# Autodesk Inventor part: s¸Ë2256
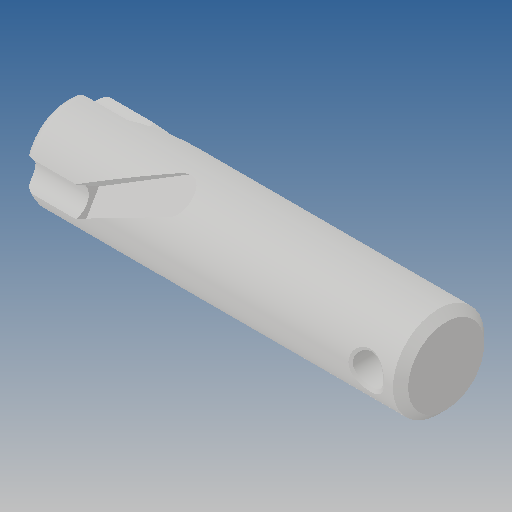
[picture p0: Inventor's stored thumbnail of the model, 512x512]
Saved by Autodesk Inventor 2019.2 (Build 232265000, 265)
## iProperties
Created: 2013-09
Part Number: s¸Ë2256
Material: Ogólny
Document SubType Name: Modeling
Designer: CADENGINEERING4
Density: 1 g/cm^3
Appearance: Domyślna
Author: CADENGINEERING4
Revision Number: ÈÎºÎ
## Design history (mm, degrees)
feature "µ¹½Ç1"
node "Bryła1"
